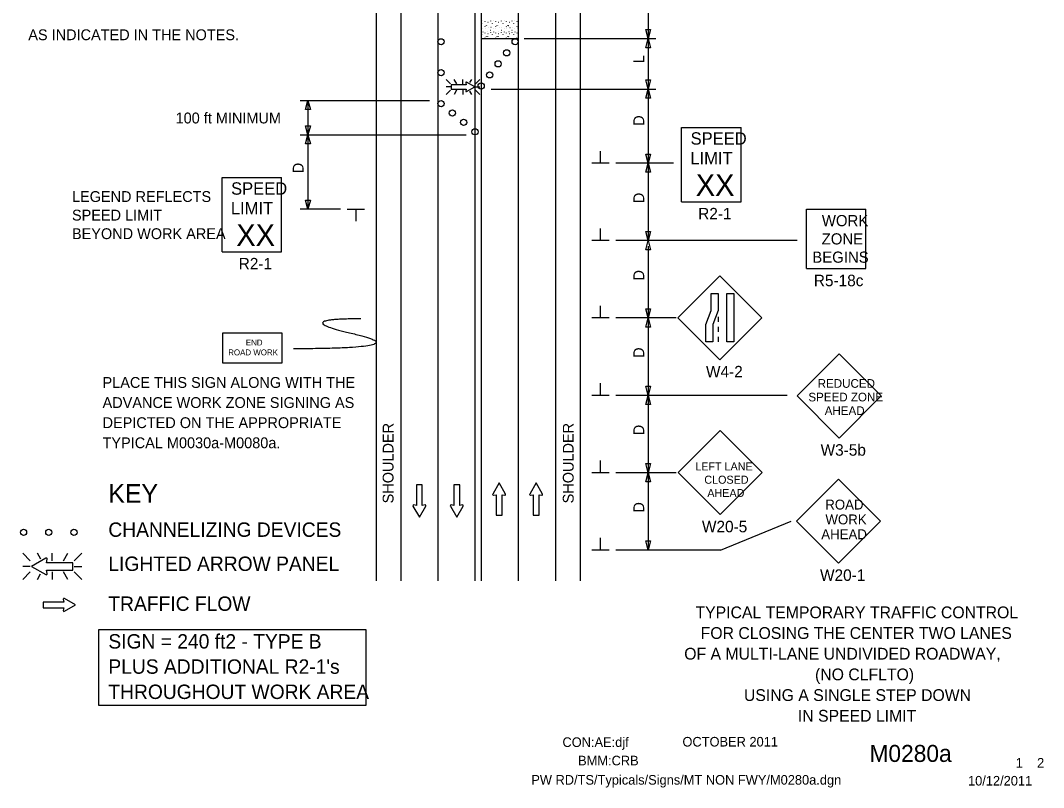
# Model space of a CAD drawing. Extents: x 16740 to 18475, y 5932 to 6927.
# Drawn here: x 16740 to 17402, y 5932 to 6428 of the extents above; entities that cross this region are included whole.
import ezdxf

# ---------------------------------------------------------------- set-up
doc = ezdxf.new("R2010")
doc.units = 0
for name, color, linetype in [('ALI_LEGAL_EX', 7, 'Continuous'), ('BORDER_SIGNAL_WO', 7, 'Continuous'), ('Level 44', 7, 'Continuous'), ('MT_SCRATCH_LEVEL_E', 7, 'Continuous'), ('PAVT_EDGE_EX', 7, 'Continuous'), ('TRAFFIC_SIGNS_PR', 7, 'Continuous'), ('TYPICAL_TEXT_DIMEN_EX', 7, 'Continuous'), ('TYPICAL_TEXT_DIMEN_PR', 7, 'Continuous')]:
    doc.layers.add(name, color=color, linetype=linetype)

msp = doc.modelspace()

# ---------------------------------------------------------------- linework, layer by layer
at = {"layer": 'ALI_LEGAL_EX'}
for p, q in [((17010.12, 6916.46), (17010.12, 6065.34)), ((17062.12, 6916.46), (17062.12, 6065.34))]:
    msp.add_line(p, q, dxfattribs=at)
for points in [[(17010.12, 6416.46), (17010.12, 6391.46)], [(17010.12, 6316.46), (17010.12, 6291.46)], [(17062.12, 6316.46), (17062.12, 6291.46)], [(17010.12, 6216.46), (17010.12, 6191.46)], [(17062.12, 6216.46), (17062.12, 6191.46)], [(17010.12, 6116.46), (17010.12, 6091.46)], [(17062.12, 6116.46), (17062.12, 6091.46)]]:
    msp.add_lwpolyline(points, dxfattribs=at)
at = {"layer": 'MT_SCRATCH_LEVEL_E'}
for p, q in [((17000.04, 6127.4), (16996.3, 6127.4)), ((16996.3, 6127.4), (16996.3, 6114.15)), ((17000.04, 6127.4), (16996.3, 6127.4)), ((16996.3, 6127.4), (16996.3, 6114.15)), ((17000.04, 6114.15), (17000.04, 6127.4)), ((17000.04, 6114.15), (17000.04, 6127.4)), ((17024.22, 6127.4), (17020.48, 6127.4)), ((17020.48, 6127.4), (17020.48, 6114.15)), ((17024.22, 6127.4), (17020.48, 6127.4)), ((17020.48, 6127.4), (17020.48, 6114.15)), ((17024.22, 6114.15), (17024.22, 6127.4)), ((17024.22, 6114.15), (17024.22, 6127.4)), ((17049.71, 6128.69), (17045.6, 6121.45)), ((17049.71, 6128.69), (17045.6, 6121.45)), ((17053.86, 6121.45), (17049.71, 6128.69)), ((17053.86, 6121.45), (17049.71, 6128.69)), ((17073.64, 6128.69), (17069.53, 6121.45)), ((17073.64, 6128.69), (17069.53, 6121.45)), ((17077.78, 6121.45), (17073.64, 6128.69)), ((17077.78, 6121.45), (17073.64, 6128.69)), ((17046.08, 6120.77), (17047.86, 6121.08)), ((17046.08, 6120.77), (17047.86, 6121.08)), ((17047.86, 6121.08), (17047.86, 6107.82)), ((17047.86, 6121.08), (17047.86, 6107.82)), ((17051.6, 6107.82), (17051.6, 6121.08)), ((17051.6, 6121.08), (17053.38, 6120.77)), ((17051.6, 6107.82), (17051.6, 6121.08)), ((17051.6, 6121.08), (17053.38, 6120.77)), ((17070.01, 6120.77), (17071.79, 6121.08)), ((17070.01, 6120.77), (17071.79, 6121.08)), ((17071.79, 6121.08), (17071.79, 6107.82)), ((17071.79, 6121.08), (17071.79, 6107.82)), ((17075.53, 6107.82), (17075.53, 6121.08)), ((17075.53, 6121.08), (17077.3, 6120.77)), ((17075.53, 6107.82), (17075.53, 6121.08)), ((17075.53, 6121.08), (17077.3, 6120.77)), ((16994.04, 6113.78), (16998.19, 6106.54)), ((16994.04, 6113.78), (16998.19, 6106.54)), ((16996.3, 6114.15), (16994.52, 6114.46)), ((16996.3, 6114.15), (16994.52, 6114.46)), ((16998.19, 6106.54), (17002.3, 6113.78)), ((16998.19, 6106.54), (17002.3, 6113.78)), ((17001.82, 6114.46), (17000.04, 6114.15)), ((17001.82, 6114.46), (17000.04, 6114.15)), ((17018.22, 6113.78), (17022.37, 6106.54)), ((17018.22, 6113.78), (17022.37, 6106.54)), ((17020.48, 6114.15), (17018.7, 6114.46)), ((17020.48, 6114.15), (17018.7, 6114.46)), ((17022.37, 6106.54), (17026.48, 6113.78)), ((17022.37, 6106.54), (17026.48, 6113.78)), ((17026, 6114.46), (17024.22, 6114.15)), ((17026, 6114.46), (17024.22, 6114.15)), ((17047.86, 6107.82), (17051.6, 6107.82)), ((17047.86, 6107.82), (17051.6, 6107.82)), ((17071.79, 6107.82), (17075.53, 6107.82)), ((17071.79, 6107.82), (17075.53, 6107.82)), ((16767.91, 6053.53), (16768.23, 6051.75)), ((16767.91, 6053.53), (16768.23, 6051.75)), ((16775.84, 6049.9), (16768.6, 6054.01)), ((16775.84, 6049.9), (16768.6, 6054.01)), ((16768.23, 6051.75), (16754.97, 6051.75)), ((16754.97, 6051.75), (16754.97, 6048.01)), ((16768.23, 6051.75), (16754.97, 6051.75)), ((16754.97, 6051.75), (16754.97, 6048.01)), ((16754.97, 6048.01), (16768.23, 6048.01)), ((16754.97, 6048.01), (16768.23, 6048.01)), ((16768.23, 6048.01), (16767.91, 6046.23)), ((16768.23, 6048.01), (16767.91, 6046.23)), ((16768.6, 6045.75), (16775.84, 6049.9)), ((16768.6, 6045.75), (16775.84, 6049.9))]:
    msp.add_line(p, q, dxfattribs=at)
for centre, start, end in [((17046.01, 6121.23), 150.42484, 279.96381), ((17046.01, 6121.23), 150.42484, 279.96381), ((17053.45, 6121.23), 260.03619, 29.77312), ((17053.45, 6121.23), 260.03619, 29.77312), ((17069.93, 6121.23), 150.42484, 279.96381), ((17069.93, 6121.23), 150.42484, 279.96381), ((17077.37, 6121.23), 260.03619, 29.77312), ((17077.37, 6121.23), 260.03619, 29.77312), ((16994.45, 6114), 80.03619, 209.77312), ((16994.45, 6114), 80.03619, 209.77312), ((17001.89, 6114), 330.42484, 99.96381), ((17001.89, 6114), 330.42484, 99.96381), ((17018.63, 6114), 80.03619, 209.77312), ((17018.63, 6114), 80.03619, 209.77312), ((17026.07, 6114), 330.42484, 99.96381), ((17026.07, 6114), 330.42484, 99.96381), ((16768.37, 6053.6), 60.42484, 189.96381), ((16768.37, 6053.6), 60.42484, 189.96381), ((16768.37, 6046.16), 170.03619, 299.77312), ((16768.37, 6046.16), 170.03619, 299.77312)]:
    msp.add_arc(centre, 0.463, start, end, dxfattribs=at)
at = {"layer": 'PAVT_EDGE_EX'}
for p, q in [((16970.12, 6916.46), (16970.12, 6065.34)), ((16986.12, 6916.46), (16986.12, 6065.34)), ((17086.12, 6916.46), (17086.12, 6065.34)), ((17102.12, 6916.46), (17102.12, 6065.34)), ((17034.12, 6439.88), (17034.12, 6065.34)), ((17038.12, 6439.88), (17038.12, 6065.34)), ((17038.6, 6425.74), (17038.65, 6425.86)), ((17039.22, 6427.5), (17039.27, 6427.42)), ((17040.5, 6426.92), (17040.51, 6426.81)), ((17041.38, 6424.51), (17041.43, 6424.43)), ((17042.12, 6424.48), (17042.17, 6424.4)), ((17042.53, 6426.58), (17042.58, 6426.5)), ((17044.31, 6427.25), (17044.36, 6427.36)), ((17045.48, 6425.74), (17045.54, 6425.86)), ((17046.1, 6427.5), (17046.15, 6427.42)), ((17047.38, 6426.92), (17047.4, 6426.81)), ((17048.27, 6424.51), (17048.32, 6424.43)), ((17049.01, 6424.48), (17049.06, 6424.4)), ((17049.41, 6426.58), (17049.47, 6426.5)), ((17051.19, 6427.25), (17051.25, 6427.36)), ((17052.37, 6425.74), (17052.42, 6425.86)), ((17052.99, 6427.5), (17053.04, 6427.42)), ((17054.27, 6426.92), (17054.28, 6426.81)), ((17055.16, 6424.51), (17055.21, 6424.43)), ((17055.89, 6424.48), (17055.94, 6424.4)), ((17056.3, 6426.58), (17056.35, 6426.5)), ((17058.08, 6427.25), (17058.13, 6427.36)), ((17059.26, 6425.74), (17059.31, 6425.86)), ((17059.88, 6427.5), (17059.93, 6427.42)), ((17061.16, 6426.92), (17061.17, 6426.81)), ((17062.04, 6424.51), (17062.1, 6424.43)), ((17038.6, 6418.46), (17038.65, 6418.58)), ((17039.17, 6422.42), (17039.22, 6422.34)), ((17039.22, 6420.21), (17039.27, 6420.14)), ((17040.5, 6419.64), (17040.51, 6419.52)), ((17040.62, 6423.55), (17040.67, 6423.66)), ((17040.7, 6422.28), (17040.75, 6422.2)), ((17041.38, 6417.22), (17041.43, 6417.15)), ((17042.12, 6417.19), (17042.17, 6417.11)), ((17042.34, 6420.49), (17042.39, 6420.61)), ((17042.53, 6419.29), (17042.58, 6419.22)), ((17042.99, 6423.1), (17043.04, 6423.02)), ((17044.26, 6421.36), (17044.32, 6421.28)), ((17044.31, 6419.96), (17044.36, 6420.08)), ((17044.44, 6423.25), (17044.49, 6423.37)), ((17045.48, 6418.46), (17045.54, 6418.58)), ((17046.05, 6422.42), (17046.11, 6422.34)), ((17046.1, 6420.21), (17046.15, 6420.14)), ((17047.38, 6419.64), (17047.4, 6419.52)), ((17047.5, 6423.55), (17047.56, 6423.66)), ((17047.58, 6422.28), (17047.64, 6422.2)), ((17048.27, 6417.22), (17048.32, 6417.15)), ((17049.01, 6417.19), (17049.06, 6417.11)), ((17049.23, 6420.49), (17049.28, 6420.61)), ((17049.41, 6419.29), (17049.47, 6419.22)), ((17049.87, 6423.1), (17049.93, 6423.02)), ((17051.15, 6421.36), (17051.2, 6421.28)), ((17051.19, 6419.96), (17051.25, 6420.08)), ((17051.32, 6423.25), (17051.37, 6423.37)), ((17052.37, 6418.46), (17052.42, 6418.58)), ((17052.94, 6422.42), (17052.99, 6422.34)), ((17052.99, 6420.21), (17053.04, 6420.14)), ((17054.27, 6419.64), (17054.28, 6419.52)), ((17054.39, 6423.55), (17054.44, 6423.66)), ((17054.47, 6422.28), (17054.52, 6422.2)), ((17055.16, 6417.22), (17055.21, 6417.15)), ((17055.89, 6417.19), (17055.94, 6417.11)), ((17056.11, 6420.49), (17056.17, 6420.61)), ((17056.3, 6419.29), (17056.35, 6419.22)), ((17056.76, 6423.1), (17056.81, 6423.02)), ((17058.04, 6421.36), (17058.09, 6421.28)), ((17058.08, 6419.96), (17058.13, 6420.08)), ((17058.21, 6423.25), (17058.26, 6423.37)), ((17059.26, 6418.46), (17059.31, 6418.58)), ((17059.83, 6422.42), (17059.88, 6422.34)), ((17059.88, 6420.21), (17059.93, 6420.14)), ((17061.16, 6419.64), (17061.17, 6419.52)), ((17061.28, 6423.55), (17061.33, 6423.66)), ((17061.36, 6422.28), (17061.41, 6422.2)), ((17062.04, 6417.22), (17062.1, 6417.15)), ((17038.12, 6415.9), (17062.12, 6415.9)), ((17040.62, 6416.26), (17040.67, 6416.38)), ((17044.44, 6415.97), (17044.49, 6416.08)), ((17047.5, 6416.26), (17047.56, 6416.38)), ((17051.32, 6415.97), (17051.37, 6416.08)), ((17054.39, 6416.26), (17054.44, 6416.38)), ((17058.21, 6415.97), (17058.26, 6416.08)), ((17061.28, 6416.26), (17061.33, 6416.38))]:
    msp.add_line(p, q, dxfattribs=at)
at = {"layer": 'TRAFFIC_SIGNS_PR'}
for p, q in [((17018.25, 6386.72), (17015.42, 6389.54)), ((17018.25, 6384.69), (17015.42, 6384.69)), ((17020.54, 6389.54), (17022.17, 6386.72)), ((17026.33, 6386.72), (17026.33, 6389.54)), ((17031.8, 6389.54), (17030.59, 6387.44)), ((17037.23, 6389.54), (17034.42, 6386.72)), ((17034.42, 6384.69), (17037.23, 6384.69)), ((17018.25, 6382.65), (17015.42, 6379.83)), ((17022.2, 6382.65), (17020.57, 6379.83)), ((17026.33, 6382.65), (17026.33, 6379.83)), ((17030.51, 6382.02), (17031.77, 6379.83)), ((17037.23, 6379.84), (17034.42, 6382.65)), ((17167.77, 6358.5), (17206.17, 6358.5)), ((17167.77, 6310.5), (17167.77, 6358.5)), ((17206.17, 6310.5), (17206.17, 6358.5)), ((16870.65, 6326.17), (16909.05, 6326.17)), ((16870.65, 6278.17), (16870.65, 6326.17)), ((16909.05, 6278.17), (16909.05, 6326.17)), ((17167.77, 6310.5), (17206.17, 6310.5)), ((17248.42, 6267.3), (17248.42, 6305.7)), ((17248.42, 6305.7), (17286.82, 6305.7)), ((17286.82, 6267.3), (17286.82, 6305.7)), ((16870.65, 6278.17), (16909.05, 6278.17)), ((17248.42, 6267.3), (17286.82, 6267.3)), ((17192.54, 6262.67), (17165.38, 6235.52)), ((17219.69, 6235.52), (17192.54, 6262.67)), ((17165.38, 6235.52), (17192.54, 6208.36)), ((17191.29, 6236.01), (17191.29, 6232.81)), ((17192.54, 6208.36), (17219.69, 6235.52)), ((17191.29, 6229.61), (17191.29, 6226.41)), ((17191.29, 6223.21), (17191.29, 6220.01)), ((17269.66, 6212.06), (17242.51, 6184.91)), ((17296.81, 6184.91), (17269.66, 6212.06)), ((17242.51, 6184.91), (17269.66, 6157.76)), ((17269.66, 6157.76), (17296.81, 6184.91)), ((17192.71, 6162.56), (17165.56, 6135.4)), ((17219.87, 6135.4), (17192.71, 6162.56)), ((17165.56, 6135.4), (17192.71, 6108.25)), ((17192.71, 6108.25), (17219.87, 6135.4)), ((17269.09, 6131.15), (17241.93, 6104)), ((17296.24, 6104), (17269.09, 6131.15)), ((17241.93, 6104), (17269.09, 6076.85)), ((17269.09, 6076.85), (17296.24, 6104)), ((16741.65, 6083.28), (16746.58, 6078.35)), ((16753.41, 6079.46), (16751.2, 6083.28)), ((16760.73, 6078.35), (16760.73, 6083.28)), ((16767.97, 6078.35), (16770.82, 6083.28)), ((16774.88, 6078.35), (16779.82, 6083.29)), ((16746.58, 6074.79), (16741.65, 6074.79)), ((16774.88, 6074.79), (16779.82, 6074.79)), ((16741.65, 6066.31), (16746.58, 6071.24)), ((16751.16, 6066.3), (16753.27, 6069.96)), ((16760.73, 6071.24), (16760.73, 6066.3)), ((16770.86, 6066.3), (16768.01, 6071.24)), ((16774.88, 6071.24), (16779.82, 6066.3))]:
    msp.add_line(p, q, dxfattribs=at)
for points in [[(17028.16, 6387.37), (17028.39, 6386.07), (17018.66, 6386.07), (17018.66, 6383.33), (17028.39, 6383.33), (17028.16, 6382.03)], [(17028.66, 6381.67), (17033.97, 6384.69), (17028.66, 6387.73)], [(16756.66, 6080.07), (16747.37, 6074.79), (16756.66, 6069.47)], [(16757.53, 6070.1), (16757.13, 6072.37), (16774.15, 6072.37), (16774.15, 6077.17), (16757.13, 6077.17), (16757.54, 6079.45)]]:
    msp.add_lwpolyline(points, dxfattribs=at)
for points in [[(17191.29, 6251.25), (17191.29, 6240.07), (17187.94, 6231.19), (17187.94, 6220.01), (17183.45, 6220.01), (17183.45, 6231.19), (17186.79, 6240.07), (17186.79, 6251.25)], [(17201.42, 6251.25), (17201.42, 6220.01), (17196.93, 6220.01), (17196.93, 6251.25)], [(16870.94, 6206.43), (16909.34, 6206.43), (16909.34, 6225.63), (16870.94, 6225.63)]]:
    msp.add_lwpolyline(points, close=True, dxfattribs=at)
for centre in [(17012.15, 6413.87), (17060.09, 6413.87), (17054.6, 6406.73), (17049.1, 6399.6), (17012.15, 6393.87), (17043.61, 6392.47), (17038.12, 6385.34), (17012.15, 6373.87), (17019.48, 6367.81), (17026.8, 6361.74), (17034.13, 6355.67), (16742.21, 6096.83), (16758.51, 6096.83), (16774.81, 6096.83)]:
    msp.add_circle(centre, 2, dxfattribs=at)
for centre, radius, start, end in [((17028.49, 6387.43), 0.341, 61.48329, 189.95933), ((17028.49, 6381.97), 0.341, 170.73078, 298.89165), ((16756.95, 6079.55), 0.598, 350.73078, 118.89165), ((16756.95, 6070), 0.597, 241.48329, 9.95933)]:
    msp.add_arc(centre, radius, start, end, dxfattribs=at)
msp.add_open_spline([(16960.4, 6234.78), (16913.17, 6234.78), (16998.19, 6215.43), (16916.71, 6215.43)], degree=2, dxfattribs=at)
at = {"layer": 'TYPICAL_TEXT_DIMEN_EX'}
msp.add_lwpolyline([(16790.87, 6034.08), (16963.49, 6034.08), (16963.49, 5984.89), (16790.87, 5984.89)], close=True, dxfattribs=at)
at = {"layer": 'TYPICAL_TEXT_DIMEN_PR'}
for p, q in [((17146.12, 6439.88), (17146.12, 6415.88)), ((17146.12, 6415.88), (17144.55, 6421.74)), ((17144.55, 6421.74), (17146.12, 6421.74)), ((17146.12, 6421.74), (17147.69, 6421.74)), ((17147.69, 6421.74), (17146.12, 6415.88)), ((17065.98, 6415.88), (17151.12, 6415.88)), ((17144.55, 6410.01), (17146.12, 6415.88)), ((17146.12, 6415.88), (17146.12, 6383.34)), ((17146.12, 6415.88), (17147.69, 6410.01)), ((17146.12, 6410.01), (17144.55, 6410.01)), ((17147.69, 6410.01), (17146.12, 6410.01)), ((17146.12, 6383.34), (17144.55, 6389.2)), ((17144.55, 6389.2), (17146.12, 6389.2)), ((17146.12, 6389.2), (17147.69, 6389.2)), ((17147.69, 6389.2), (17146.12, 6383.34)), ((17044.68, 6383.34), (17151.12, 6383.34)), ((17144.55, 6377.47), (17146.12, 6383.34)), ((17146.12, 6377.47), (17144.55, 6377.47)), ((17146.12, 6383.34), (17146.12, 6335.34)), ((17146.12, 6383.34), (17147.69, 6377.47)), ((17147.69, 6377.47), (17146.12, 6377.47)), ((16921.12, 6375.88), (17004.78, 6375.88)), ((16924.55, 6370.01), (16926.12, 6375.88)), ((16926.12, 6375.88), (16926.12, 6353.68)), ((16926.12, 6375.88), (16927.69, 6370.01)), ((16926.12, 6370.01), (16924.55, 6370.01)), ((16927.69, 6370.01), (16926.12, 6370.01)), ((16926.12, 6353.68), (16924.55, 6359.55)), ((16924.55, 6359.55), (16926.12, 6359.55)), ((16926.12, 6359.55), (16927.69, 6359.55)), ((16927.69, 6359.55), (16926.12, 6353.68)), ((16921.12, 6353.68), (17028.42, 6353.68)), ((16924.55, 6347.82), (16926.12, 6353.68)), ((16926.12, 6353.68), (16926.12, 6305.69)), ((16926.12, 6353.68), (16927.69, 6347.82)), ((16926.12, 6353.68), (16926.12, 6305.69)), ((16926.12, 6347.82), (16924.55, 6347.82)), ((16927.69, 6347.82), (16926.12, 6347.82)), ((17115.24, 6335.34), (17115.24, 6343.13)), ((17146.12, 6335.34), (17144.55, 6341.21)), ((17144.55, 6341.21), (17146.12, 6341.21)), ((17146.12, 6341.21), (17147.69, 6341.21)), ((17147.69, 6341.21), (17146.12, 6335.34)), ((17120.87, 6335.34), (17109.62, 6335.34)), ((17162.41, 6335.34), (17125.12, 6335.34)), ((17144.55, 6329.48), (17146.12, 6335.34)), ((17146.12, 6335.34), (17146.12, 6285.34)), ((17146.12, 6335.34), (17147.69, 6329.48)), ((17146.12, 6329.48), (17144.55, 6329.48)), ((17147.69, 6329.48), (17146.12, 6329.48)), ((16926.12, 6305.69), (16924.55, 6311.55)), ((16924.55, 6311.55), (16926.12, 6311.55)), ((16926.12, 6311.55), (16927.69, 6311.55)), ((16927.69, 6311.55), (16926.12, 6305.69)), ((16947.12, 6305.69), (16921.12, 6305.69)), ((16951.37, 6305.69), (16962.62, 6305.69)), ((16956.99, 6305.69), (16956.99, 6297.91)), ((17115.24, 6285.34), (17115.24, 6293.13)), ((17120.87, 6285.34), (17109.62, 6285.34)), ((17242.38, 6285.34), (17125.12, 6285.34)), ((17146.12, 6285.34), (17144.55, 6291.21)), ((17144.55, 6291.21), (17146.12, 6291.21)), ((17144.55, 6279.48), (17146.12, 6285.34)), ((17146.12, 6291.21), (17147.69, 6291.21)), ((17147.69, 6291.21), (17146.12, 6285.34)), ((17146.12, 6285.34), (17147.69, 6279.48)), ((17146.12, 6279.48), (17144.55, 6279.48)), ((17146.12, 6281.81), (17146.12, 6231.81)), ((17147.69, 6279.48), (17146.12, 6279.48)), ((17115.24, 6235.34), (17115.24, 6243.13)), ((17146.12, 6235.34), (17144.55, 6241.21)), ((17144.55, 6241.21), (17146.12, 6241.21)), ((17146.12, 6241.21), (17147.69, 6241.21)), ((17147.69, 6241.21), (17146.12, 6235.34)), ((17120.87, 6235.34), (17109.62, 6235.34)), ((17164.12, 6235.34), (17125.12, 6235.34)), ((17144.55, 6229.48), (17146.12, 6235.34)), ((17146.12, 6235.34), (17146.12, 6185.34)), ((17146.12, 6235.34), (17147.69, 6229.48)), ((17146.12, 6229.48), (17144.55, 6229.48)), ((17147.69, 6229.48), (17146.12, 6229.48)), ((17115.24, 6185.34), (17115.24, 6193.13)), ((17146.12, 6185.34), (17144.55, 6191.21)), ((17144.55, 6191.21), (17146.12, 6191.21)), ((17146.12, 6191.21), (17147.69, 6191.21)), ((17147.69, 6191.21), (17146.12, 6185.34)), ((17120.87, 6185.34), (17109.62, 6185.34)), ((17235.95, 6185.34), (17125.12, 6185.34)), ((17144.55, 6179.48), (17146.12, 6185.34)), ((17146.12, 6179.48), (17144.55, 6179.48)), ((17146.12, 6185.34), (17146.12, 6135.34)), ((17146.12, 6185.34), (17147.69, 6179.48)), ((17147.69, 6179.48), (17146.12, 6179.48)), ((17115.24, 6135.34), (17115.24, 6143.13)), ((17146.12, 6135.34), (17144.55, 6141.21)), ((17144.55, 6141.21), (17146.12, 6141.21)), ((17146.12, 6141.21), (17147.69, 6141.21)), ((17147.69, 6141.21), (17146.12, 6135.34)), ((17120.87, 6135.34), (17109.62, 6135.34)), ((17164.12, 6135.34), (17125.12, 6135.34)), ((17144.55, 6129.48), (17146.12, 6135.34)), ((17146.12, 6135.34), (17146.12, 6085.34)), ((17146.12, 6135.34), (17147.69, 6129.48)), ((17146.12, 6129.48), (17144.55, 6129.48)), ((17147.69, 6129.48), (17146.12, 6129.48)), ((17192.94, 6085.34), (17238.51, 6103.99)), ((17115.24, 6085.34), (17115.24, 6093.13)), ((17146.12, 6085.34), (17144.55, 6091.21)), ((17144.55, 6091.21), (17146.12, 6091.21)), ((17146.12, 6091.21), (17147.69, 6091.21)), ((17147.69, 6091.21), (17146.12, 6085.34)), ((17120.87, 6085.34), (17109.62, 6085.34)), ((17192.94, 6085.34), (17125.12, 6085.34))]:
    msp.add_line(p, q, dxfattribs=at)

# ---------------------------------------------------------------- texts
at = {"layer": 'BORDER_SIGNAL_WO'}
for s, height, p in [('CON:AE:djf', 6.2, (17090.69, 5958.06)), ('    OCTOBER 2011    ', 6.2, (17159.08, 5958.34)), ('    M0280a   ', 11, (17272.86, 5948.38)), ('BMM:CRB   ', 6.2, (17100.81, 5946.17)), (' 1    2 ', 6.2, (17381.45, 5944.7)), ('PW RD/TS/Typicals/Signs/MT NON FWY/M0280a.dgn    ', 6.2, (17070.55, 5933.71)), ('10/12/2011    ', 6.2, (17352.93, 5933.13))]:
    msp.add_text(s, height=height, dxfattribs=at).set_placement(p)
at = {"layer": 'Level 44'}
for s, p in [('TYPICAL TEMPORARY TRAFFIC CONTROL', (17176.72, 6041.25)), ('FOR CLOSING THE CENTER TWO LANES', (17180.06, 6027.88)), ('OF A MULTI-LANE UNDIVIDED ROADWAY, ', (17169.43, 6014.51)), ('(NO CLFLTO)', (17254.01, 6001.14)), ('USING A SINGLE STEP DOWN', (17208.06, 5987.77)), ('IN SPEED LIMIT', (17242.93, 5974.4))]:
    msp.add_text(s, height=7.6293, dxfattribs=at).set_placement(p)
at = {"layer": 'TRAFFIC_SIGNS_PR'}
for s, height, p in [('AS INDICATED IN THE NOTES.', 7, (16745.28, 6414.9)), ('SPEED', 8, (17173.54, 6347.37)), ('LIMIT', 8, (17173.38, 6334.57)), ('XX', 14.031, (17176.88, 6314.26)), ('SPEED', 8, (16876.42, 6315.03)), ('LIMIT', 8, (16876.26, 6302.23)), ('R2-1', 7.44, (17178.45, 6299.06)), ('WORK', 7.217, (17258.42, 6294.67)), ('XX', 14.031, (16879.77, 6281.93)), ('ZONE', 7.217, (17258.3, 6282.86)), ('BEGINS', 7.217, (17252.23, 6271.05)), ('R2-1', 7.44, (16881.33, 6266.73)), ('R5-18c', 7.44, (17253.23, 6255.86)), ('END', 3.831, (16885.94, 6217.56)), ('ROAD WORK', 3.831, (16874.55, 6211.18)), ('W4-2', 7.44, (17183.49, 6196.93)), ('PLACE THIS SIGN ALONG WITH THE', 7, (16793.3, 6190.16)), ('REDUCED', 5.6, (17255.72, 6190.22)), ('SPEED ZONE', 5.6, (17249.71, 6181.42)), ('ADVANCE WORK ZONE SIGNING AS', 7, (16793.3, 6177.16)), ('AHEAD', 5.6, (17260.27, 6172.62)), ('DEPICTED ON THE APPROPRIATE', 7, (16793.3, 6164.16)), ('TYPICAL M0030a-M0080a.', 7, (16793.3, 6151.16)), ('W3-5b', 7.44, (17257.61, 6146.32)), ('LEFT LANE', 5.2, (17176.59, 6136.8)), ('CLOSED', 5.2, (17182.43, 6128.2)), ('AHEAD', 5.2, (17184.37, 6119.6)), ('ROAD', 6.4, (17260.63, 6111.53)), ('WORK', 6.4, (17260.74, 6101.93)), ('W20-5', 7.44, (17180.89, 6096.81)), ('AHEAD', 6.4, (17258.05, 6092.33)), ('W20-1', 7.44, (17257.25, 6065.41))]:
    msp.add_text(s, height=height, dxfattribs=at).set_placement(p)
at = {"layer": 'TYPICAL_TEXT_DIMEN_EX'}
for s, height, p in [('KEY', 12, (16797.05, 6115.93)), ('CHANNELIZING DEVICES', 9.3, (16797.05, 6093.88)), ('LIGHTED ARROW PANEL', 9.3, (16797.05, 6071.83)), ('TRAFFIC FLOW', 9.3, (16797.05, 6046.03)), ('SIGN = 240 ft2 - TYPE B', 9.3, (16797.05, 6021.67)), ("PLUS ADDITIONAL R2-1's", 9.3, (16797.05, 6005.37)), ('THROUGHOUT WORK AREA', 9.3, (16797.05, 5989.07))]:
    msp.add_text(s, height=height, dxfattribs=at).set_placement(p)
at = {"layer": 'TYPICAL_TEXT_DIMEN_PR'}
for s, p in [('L', (17143.56, 6399.97)), ('D', (17143.56, 6359.56)), ('D', (16923.29, 6328.91)), ('D', (17143.56, 6309.56)), ('D', (17143.56, 6259.56)), ('D', (17143.56, 6209.56)), ('SHOULDER', (16981.44, 6115.5)), ('SHOULDER', (17097.93, 6115.5)), ('D', (17143.56, 6159.56)), ('D', (17143.56, 6109.56))]:
    msp.add_text(s, height=7, rotation=90, dxfattribs=at).set_placement(p)
for s, p in [('100 ft MINIMUM', (16840.53, 6361.09)), ('LEGEND REFLECTS', (16773.53, 6310.32)), ('SPEED LIMIT', (16773.53, 6298.32)), ('BEYOND WORK AREA', (16773.53, 6286.32))]:
    msp.add_text(s, height=7, dxfattribs=at).set_placement(p)

doc.saveas('drawing.dxf')
